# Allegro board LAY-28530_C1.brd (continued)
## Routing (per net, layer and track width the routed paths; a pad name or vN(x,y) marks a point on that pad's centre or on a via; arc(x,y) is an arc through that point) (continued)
LANED_RX_N: length 90.8
  TOP w0.104: v1(127.9,83.87) 127.81,83.77 127.66,83.77 127.5,83.93 127.5,87.74 131.68,91.92 131.68,117.7 135.74,121.76 135.74,129.54 132.75,132.53 132.11,132.53 C30.1 ; U21.AB14 133,62.41 132.6,62.02 130.77,62.02 130.76,62.02 129.77,62.02 128.37,60.63 126.76,60.63 125.99,61.39 125.99,63.37 127.26,64.64 127.26,64.87 v1(127.06,65.07)
  L3_INT1 w0.104: v1(127.9,83.87) 127.79,83.87 127.48,84.18 127.48,84.48 127.07,84.88 126.42,84.88 125.91,84.38 125.91,83.36 126.29,82.98 126.79,82.98 127.82,81.95 127.82,67.37 127.25,66.81 127.25,65.27 v1(127.06,65.07)
LANED_RX_P: length 87.4
  TOP w0.104: U21.AC14 132.2,62.41 132.03,62.24 131.76,62.24 131.67,62.33 130.77,62.33 130.76,62.32 129.64,62.32 128.25,60.93 126.88,60.93 126.29,61.52 126.29,63.25 127.56,64.52 127.56,64.82 v1(127.82,65.07) ; C37.1 132.11,132.23 132.62,132.23 135.44,129.42 135.44,121.89 131.37,117.82 131.37,92.04 127.2,87.87 127.2,84.14 126.93,83.87 v1(126.8,83.87)
  L3_INT1 w0.104: v1(126.8,83.87) 127.11,84.18 127.11,84.32 126.92,84.51 126.58,84.51 126.28,84.22 126.28,83.51 126.45,83.35 126.94,83.35 128.19,82.1 128.19,67.22 127.62,66.65 127.62,65.27 v1(127.82,65.07)
LANED_TX_N: length 82.1
  TOP w0.104: v1(126.51,82.47) 126.11,82.87 126.11,88 130.53,92.43 130.53,118.54 134.73,122.73 134.73,129.41 133.23,130.91 129.68,130.91 128.2,132.38 127.59,132.38 U6.39
  L3_INT1 w0.104: v1(126.51,82.47) 126.16,82.12 126.16,70.94 127.06,70.04 127.06,67.74 v1(127.18,67.61)
  BOTTOM w0.104: C417.1 129.09,62.09 128.98,61.98 128.49,61.98 128.33,62.15 128.33,62.66 126.6,64.39 126.6,65.25 126.95,65.6 126.95,67.38 v1(127.18,67.61)
LANED_TX_P: length 82.1
  TOP w0.104: U6.38 128.17,131.98 129.55,130.6 133.11,130.6 134.42,129.29 134.42,122.86 130.23,118.67 130.23,92.55 125.8,88.12 125.8,82.87 v1(125.41,82.47)
  L3_INT1 w0.104: v1(125.41,82.47) 125.79,82.09 125.79,70.79 126.69,69.89 126.69,67.88 v1(126.42,67.61)
  BOTTOM w0.104: v1(126.42,67.61) 126.65,67.38 126.65,65.73 126.29,65.37 126.29,64.26 128.02,62.53 128.02,62.03 128.37,61.68 128.98,61.68 129.09,61.58 C429.1
LDO_1V0: length 27.5
  TOP w0.305: U26.4 108.01,55.04 v1(108.26,55.29)
  TOP w0.508: 110.29,54.91 R137.2 111.82,56.56 v1(115.75,60.5)
  BOTTOM w0.381: R309.2 v1(120.33,70.91)
  BOTTOM w0.508: FL1.3 116.22,60.97 v1(115.75,60.5) 115.12,60.5 114.48,61.14 114.48,63.04 116.13,64.69 116.13,69.19 117.4,70.46 119.87,70.46 v1(120.33,70.91)
LED_G-: length 25.2
  TOP w0.305: J3.16 144.71,163.16 144.71,154.23 144.33,153.85 144.33,146.1 145.09,145.34 C18.1 R26.2
LED_GY+: length 44.2
  TOP w0.254: J3.17 144.48,165.92 146.27,164.13 157.72,164.13 J3.19
  TOP w0.508: J3.17 142.95,165.93 141.28,164.26 L10.2
LED_Y-: length 26.2
  TOP w0.305: J3.18 159.31,163.19 159.31,150.29 165.28,144.32 C16.1 R24.2
MPCIE1_CLK+: length 43.7
  TOP w0.104: P3.13 57.22,126.78 57.47,126.53 57.98,126.53 59.11,125.4 59.11,94.79 61.83,92.08 61.83,88.8 61.93,88.69 R352.1 R351.2
MPCIE1_CLK-: length 43.3
  TOP w0.104: P3.11 57.15,125.98 57.4,126.23 57.85,126.23 58.81,125.27 58.81,94.67 61.52,91.95 61.52,88.82 61.4,88.69 R358.1 R357.2
MPCIE2_CLK+: length 28.6
  TOP w0.104: P2.13 43.55,65.01 43.8,65.25 43.8,65.68 44.25,66.14 59.24,66.14 61.1,67.99 61.1,73.96 60.97,74.09 R334.1 R333.2
MPCIE2_CLK-: length 28.6
  TOP w0.104: R347.2 R348.1 61.52,74.09 61.4,73.96 61.4,67.87 59.37,65.83 44.38,65.83 44.1,65.56 44.1,65.22 44.35,64.97 P2.11
NAND_BOOT_SEL: length 54.8
  TOP w0.127: v1(179.9,89.59) 179.89,89.6 179.89,90.73
  TOP w0.152: v1(203,58.24) 203,58.25 SW3.4
  L3_INT1 w0.127: v1(179.9,89.59) 181.03,90.73 194.62,90.73 203,82.34 v1(203,58.24)
  BOTTOM w0.127: U15.1 v1(179.9,89.59)
NAND_CS: length 22.6
  TOP w0.127: U16.C6 v2(195.26,86.26)
  L3_INT1 w0.127: v1(182.5,89.46) 183.39,90.35 194.49,90.35 195.64,89.2 195.64,86.64 v2(195.26,86.26)
  BOTTOM w0.152: v1(182.5,89.46) U15.5 182.5,91.93 182.3,92.12 181.41,92.12 181.2,91.91 U15.3
NAND_RB: length 15.4
  TOP w0.152: v1(182.56,83.49) 183.44,82.6 193.73,82.6 194.63,83.49 U16.C8
  BOTTOM w0.152: U15.12 182.5,83.54 v1(182.56,83.49)
NOR_CS: length 21
  TOP w0.152: v1(177.39,77.43) U20.32
  L3_INT1 w0.127: v1(177.39,77.43) 178.75,78.79 178.75,86.76 v1(180.55,88.57)
  BOTTOM w0.152: v1(180.55,88.57) U15.2 180.55,92.15 180.9,92.5 182.68,92.5 183.15,92.04 U15.6
NOR_RB: length 21.6
  TOP w0.152: U20.17 v1(199.3,73.43)
  L3_INT1 w0.122: 190.52,82.22 189.25,83.49 186.37,83.49
  L3_INT1 w0.127: v1(199.3,73.43) 190.52,82.22 ; 186.37,83.49 v1(184.46,83.49)
  BOTTOM w0.127: U15.9 184.45,83.5 v1(184.46,83.49)
NUART_CTS: length 10.4
  TOP w0.152: L3.2 184.84,155.12 180.57,159.39 P1.8
NUART_RTS: length 23.2
  TOP w0.152: P1.1 173.43,165.93 173.79,166.29 180.02,166.29 181.79,164.51 181.79,158.8 185.48,155.12 185.48,153.97 L5.2
PCIE_3V3: length 13
  TOP w0.508: P2.24 v1(35.95,57.41) ; P2.39 v1(29.95,62.07) ; P2.52 v1(24.75,57.33) ; P2.41 v1(29.15,62.04) ; P2.2 v1(47.95,57.44)
  BOTTOM w0.381: C306.1 36,57.36 v1(35.95,57.41) ; v1(24.75,57.33) 24.82,57.25 C307.1 ; v1(47.95,57.44) 48.06,57.33 48.06,56.56
  BOTTOM w0.508: C300.1 29.06,61.95 v1(29.15,62.04)
  vias: v1(72.7,50.47) v1(72.7,49.07) v1(73.34,49.83) v1(73.97,50.47) v1(73.97,49.07)
POE_12V: length 41.2
  TOP w0.508: v1(68.76,110.67) 68.13,110.03 R235.2 ; D10.A v1(83.5,95.43)
  L3_INT1 w0.508: v1(86.16,113.46) 83.5,110.79 v1(83.5,95.43)
  BOTTOM w0.508: v1(68.76,110.67) 70.29,112.19 82.1,112.19 82.61,112.7 R61.1 v1(86.16,113.46)
PORESET: length 47.8
  TOP w0.127: U21.B5 149,69.61 v2(149.4,70.01)
  L4_INT2 w0.127: v2(149.4,70.01) 149.92,70.53 157.16,70.53 157.92,69.77 157.92,62.66 169.35,51.23 v1(169.35,49.45)
  BOTTOM w0.152: Q24.3 Q25.3 R356.2 171.89,46.91 v1(169.35,49.45)
RESET: length 481.3
  TOP w0.152: U3.2 207.64,143.62 R15.1 207.7,142.8 v1(207.45,142.54) ; U6.13 121.17,135.98 120.96,136.19 120.96,137.59 121.21,137.84 v1(121.21,138.48) ; P2.22 v1(36.75,58.98) ; U5.13 99.84,135.98 v1(99.62,136.19) ; v1(206.18,31.29) 206.69,31.8 Q11.2 ; P3.22 v1(50.3,133.58) ; Q13.2 v1(195.64,13.71)
  L3_INT1 w0.127: v1(207.45,142.54) 206.94,142.54 203.76,139.37 203.76,97.33 210.5,90.6 210.5,63.8 209.35,62.66 209.35,36.75 206.18,33.58 v1(206.18,31.29) ; v1(99.62,136.19) 98.48,137.34 86.04,137.34 85.02,138.35 60,138.35 58.86,139.49 53.02,139.49 51.49,137.97 51.49,134.77 v1(50.3,133.58) 50.3,125.83 53.65,122.48 53.65,95.04 56.19,92.5 56.19,70.28 53.02,67.1 32.19,67.1 31.68,66.6 31.68,62.28 34.98,58.98 v1(36.75,58.98)
  L4_INT2 w0.127: v1(208.72,147.57) 208.26,147.11 171.25,147.11 168.2,144.07 142.04,144.07 137.22,139.24 123.75,139.24 122.99,138.48 v1(121.21,138.48) 120.2,139.49 116.64,139.49 115.88,138.73 111.82,138.73 109.28,136.19 v1(99.62,136.19)
  BOTTOM w0.152: v1(207.45,142.54) 207.7,142.8 Q15.2 208.59,147.7 v1(208.72,147.57) 209.28,147.57 210.24,146.61 212.65,146.61 212.91,146.86 Q14.2 ; Q25.2 174.17,37.89 176.59,35.48 182.94,35.48 184.59,33.83 200.97,33.83 203.51,31.29 v1(206.18,31.29) 206.18,20.5 199.4,13.71 v1(195.64,13.71)
RS232_CTS0: length 3
  TOP w0.152: L3.1 183.07,154.48 182.95,154.35 v1(182.94,154.35) 182.94,154.34 182.43,153.84 U2.8
RS232_RTS0: length 2.8
  TOP w0.152: L5.1 v1(182.68,153.34) 182.53,153.18 U2.7
RS232_RXD0: length 2.3
  TOP w0.152: U2.13 172.59,151.23 172.4,151.43 L6.1
RS232_TXD0: length 2.4
  TOP w0.152: L7.1 172.4,150.29 172.69,150.58 U2.14
RTC_INT_N: length 64.3
  TOP w0.152: U10.7 107.94,114.15 v1(108.01,114.22) 108.13,114.35 108.13,115.11 ; U21.R4 v2(138.19,70.81)
  L3_INT1 w0.127: v1(108.01,114.22) 108.64,114.22 112.71,110.16 112.71,102.41 126.8,88.31 129.98,88.31 131.88,86.41 131.88,82.47 132.77,81.58 132.77,79.8 133,79.58 133,70.56 133.15,70.41 136.76,70.41 136.77,70.41 137.79,70.41 v2(138.19,70.81)
RTC_XI: length 4
  TOP w0.254: Y4.1 106.48,106.73 107.29,107.53 U10.1
RTC_XO: length 4.2
  TOP w0.254: U10.2 107.94,107.56 109.02,106.47 Y4.2
SD_CLK: length 22.5
  TOP w0.152: U32.3 v1(185.44,23.58) ; v1(181.75,27.65) U30.8 U30.1 181.75,31.12 182.3,31.67 v1(182.3,31.71)
  BOTTOM w0.152: v1(182.3,31.71) 184.04,31.71 184.43,31.32 184.43,30 J16.5 ; v1(185.44,23.58) 183,23.58 182.85,23.74 182.85,23.9 183,24.05 183.93,24.05 184.08,24.2 184.08,24.41 183.93,24.56 182.07,24.56 181.92,24.71 181.92,24.91 182.07,25.07 183.95,25.07 184.08,25.19 184.08,25.45 183.95,25.58 182.58,25.58 181.75,26.41 v1(181.75,27.65)
SD_CLK1_N: length 37.3
  TOP w0.104: R113.2 103.82,80.37 103.92,80.48 105.11,80.48 105.21,80.37 ; 105.21,80.37 R114.1 ; 105.21,80.37 105.32,80.48 107.41,80.48 108.13,79.76 108.13,78.28 109.02,77.39 112.03,77.39 119.82,69.6 123.04,69.6 124.39,68.25 131.17,68.25 131.25,68.17 131.25,68.17 131.81,67.61 132.6,67.61 U21.AB7
SD_CLK1_P: length 36.5
  TOP w0.104: 131.46,68.38 131.36,68.49 131.36,68.49 131.3,68.55 124.52,68.55 123.17,69.9 119.95,69.9 112.15,77.69 109.15,77.69 108.44,78.4 108.44,79.88 107.54,80.78 105.32,80.78 105.21,80.89 ; 105.21,80.89 R111.1 ; 105.21,80.89 105.11,80.78 103.92,80.78 103.82,80.89 R110.2 ; U21.AC7 132.03,67.84 131.91,67.84 131.63,68.12 131.63,68.22
  TOP w0.127: 131.63,68.22 131.46,68.38
SD_CLK2_N: length 40.4
  TOP w0.102: 131.38,60.37 132.08,60.37 132.09,60.38 132.35,60.38 132.78,60.81 133,60.81 U21.AB16
  TOP w0.104: 105.34,76.44 105.44,76.54 111.14,76.54 123.45,64.23 123.45,61.06 124.95,59.56 129.09,59.56 129.9,60.37 131.37,60.37 ; 105.34,76.44 R122.1 ; 105.34,76.44 105.24,76.54 103.92,76.54 103.82,76.44 R121.2
SD_CLK2_P: length 39.5
  TOP w0.102: U21.AC16 132.2,60.81 131.99,60.6 131.47,60.6 131.4,60.68 131.37,60.68
  TOP w0.104: 131.37,60.68 129.77,60.68 128.96,59.87 125.07,59.87 123.75,61.18 123.75,64.36 111.27,76.84 105.44,76.84 105.34,76.95 ; 105.34,76.95 R117.1 ; 105.34,76.95 105.24,76.84 103.92,76.84 103.82,76.95 R116.2
SD_CMD: length 23.7
  TOP w0.152: v1(181.03,31.67) 181.25,31.45 U30.2 U30.7 181.25,26.75 182.47,25.53 U32.6
  BOTTOM w0.152: J16.2 191.93,28.85 191.57,28.5 186.37,28.5 185.73,29.13 185.73,31.04 184.33,32.43 181.79,32.43 v1(181.03,31.67)
SD_D0: length 22
  TOP w0.152: v1(179.89,31.67) 180.05,31.51 U30.3 U30.6 180.05,28.08 180.14,27.99 180.73,27.99 180.85,27.86 180.85,27.68 180.65,27.48 179.48,27.48 179.35,27.35 179.35,27.13 179.51,26.97 180.31,26.97 182.02,25.26 182.02,25.04 181.91,24.93 181.7,24.93 180.07,26.56 179.73,26.56 179.61,26.44 179.61,26.23 180.14,25.71 180.15,25.71 181.25,24.61 181.25,24.39 181.14,24.29 180.93,24.29 179.03,26.18 178.11,26.18
  BOTTOM w0.152: J16.7 179.5,30 179.5,31.28 v1(179.89,31.67)
SD_D1: length 22.6
  TOP w0.152: v1(178.62,31.63) 178.92,31.63 179.55,30.99 U30.4 U30.5 179.55,28.41 v1(179.38,28.24) ; 178.11,24.23 v1(176.91,24.23)
  BOTTOM w0.152: v1(179.38,28.24) 179.38,27.51 178.72,26.85 176.46,26.85 176.33,26.72 176.33,26.46 176.46,26.34 178.97,26.34 179.13,26.18 179.13,25.98 178.97,25.83 176.59,25.83 176.46,25.7 176.46,25.45 176.59,25.32 178.47,25.32 178.62,25.17 178.62,24.97 178.47,24.81 177.09,24.81 176.91,24.63 v1(176.91,24.23) ; J16.8 177.8,31.1 178.32,31.63 v1(178.62,31.63)
SD_D2: length 23.2
  TOP w0.152: v1(194.11,32.05) 193.43,31.37 U31.1 U31.8 v1(193.43,28.79) ; U33.3 v1(195.72,23.58)
  BOTTOM w0.152: J16.9 196.93,30 196.93,31.14 196.02,32.05 v1(194.11,32.05) ; v1(193.43,28.79) 194.11,28.12 194.11,26.59 193.86,26.34 191.98,26.34 191.83,26.18 191.83,25.98 191.98,25.83 193.71,25.83 193.86,25.68 193.86,25.52 193.71,25.37 192.11,25.37 191.95,25.22 191.95,24.97 192.11,24.81 194.49,24.81 v1(195.72,23.58)
SD_D3: length 19.1
  TOP w0.152: U33.6 191,25.53 190.74,25.8 190.74,26.01 190.94,26.21 192.33,26.21 192.59,26.46 192.59,26.85 192.46,26.97 190.56,26.97 190.43,27.1 190.43,27.61 190.56,27.73 192.59,27.73 192.93,28.08 U31.7 U31.2 192.93,31.71 v1(192.72,31.93)
  BOTTOM w0.152: J16.1 194.43,30 194.43,31.1 194.11,31.42 193.22,31.42 v1(192.72,31.93)
SDHC_CD_N: length 91.3
  TOP w0.127: U21.H3 v2(144.6,71.61)
  TOP w0.152: R156.1 v1(191.19,31.93) 191.32,31.93 191.74,31.51 U31.3 U31.6 ; v1(198.56,31.29) 198.63,31.37 Q29.3
  L3_INT1 w0.127: v1(191.19,31.93) 192.97,30.15 197.41,30.15 v1(198.56,31.29)
  L4_INT2 w0.127: v2(144.6,71.61) 144.65,71.61 145.05,71.21 157.75,71.21 158.62,70.34 158.62,62.98 170.24,51.36 170.24,37.89 175.32,32.81 190.3,32.81 v1(191.19,31.93)
  BOTTOM w0.152: J16.3A 190.23,30.96 v1(191.19,31.93)
SDHC_CLK: length 83.1
  TOP w0.152: U32.4 185.15,24.23 185.48,24.56 185.48,30.91 184.71,31.67 R160.2 185.73,32.81 185.98,33.07 v1(185.98,35.61)
  L4_INT2 w0.127: v1(158.55,76.88) 159.82,75.61 159.82,73.2 161.22,71.8 161.22,64.82 163,63.04 166.05,63.04 166.17,62.91 166.17,62.66 166.05,62.53 164.14,62.53 164.01,62.41 164.01,62.15 164.14,62.02 166.05,62.02 166.17,61.9 166.17,61.64 166.05,61.52 165.28,61.52 165.16,61.39 165.16,61.14 165.28,61.01 166.81,61.01 166.93,60.88 166.93,60.63 166.81,60.5 166.17,60.5 166.05,60.37 166.05,60.12 166.17,59.99 167.19,59.99 167.32,59.87 167.32,58.72 172.9,53.13 172.9,39.55 177.09,35.35 185.73,35.35 v1(185.98,35.61)
  BOTTOM w0.152: R282.1 158.17,77.26 v1(158.55,76.88)
SDHC_CMD: length 94.5
  TOP w0.127: U21.J2 v2(143.8,72.41)
  TOP w0.152: v1(181.92,33.7) 181.92,33.2 182.3,32.81 R159.2 183.06,28.12 182.17,27.23 182.17,26.72 182.71,26.18 U32.7
  L4_INT2 w0.127: v2(143.8,72.41) 144.2,72.81 150.69,72.81 151.57,71.93 158.3,71.93 159.31,70.91 159.31,64.31 171,52.63 171,38.15 175.57,33.58 179.25,33.58 179.38,33.7 179.38,34.08 179.51,34.21 179.76,34.21 179.89,34.08 179.89,33.7 180.02,33.58 180.27,33.58 180.4,33.7 180.4,34.08 180.52,34.21 180.78,34.21 180.9,34.08 180.9,33.7 181.03,33.58 181.29,33.58 181.41,33.7 181.41,34.08 181.54,34.21 188.65,34.21 188.78,34.08 188.78,33.83 188.65,33.7 v1(181.92,33.7)
SDHC_D0: length 96.1
  TOP w0.127: U21.J1 v2(143.8,73.21)
  TOP w0.152: v1(178.75,34.08) 178.75,33.45 178.11,32.81 R158.2 176.84,32.18 176.84,31.8 176.97,31.67 177.73,31.67 177.86,31.54 177.86,31.29 177.73,31.16 176.97,31.16 176.84,31.04 176.84,30.78 176.97,30.66 178.47,30.66 178.62,30.5 178.62,30.27 178.36,30.02 176.97,30.02 176.84,29.89 176.84,29.51 176.97,29.39 178.36,29.39 178.49,29.26 178.49,29 178.36,28.88 176.97,28.88 176.84,28.75 176.84,28.37 176.97,28.24 177.98,28.24 178.11,28.12 178.11,27.86 177.98,27.73 177.09,27.73 176.84,27.48 176.84,27.1 177.11,26.84 178.11,26.84
  L4_INT2 w0.127: v1(178.75,34.08) 178.49,33.83 175.82,33.83 171.38,38.28 171.38,52.75 159.7,64.44 159.7,71.04 157.54,73.2 157.28,73.2 157.16,73.07 157.16,72.44 157.03,72.31 156.77,72.31 156.65,72.44 156.65,73.45 156.39,73.71 155.5,73.71 155.38,73.58 155.38,72.44 155.25,72.31 155,72.31 154.87,72.44 154.87,73.45 154.62,73.71 153.73,73.71 153.6,73.58 153.6,72.44 153.47,72.31 153.22,72.31 153.09,72.44 153.09,73.58 152.96,73.71 152.71,73.71 152.58,73.58 152.58,72.44 152.46,72.31 152.2,72.31 152.08,72.44 152.08,73.58 151.95,73.71 151.69,73.71 151.57,73.58 151.57,73.07 151.44,72.95 151.19,72.95 151.06,73.07 151.06,73.58 150.93,73.71 150.68,73.71 150.55,73.58 150.55,73.33 150.42,73.2 150.17,73.2 150.04,73.33 150.04,73.58 149.92,73.71 147.38,73.71 147.25,73.58 147.25,73.33 147.12,73.2 146.87,73.2 146.74,73.33 146.74,73.58 146.61,73.71 144.3,73.71 v2(143.8,73.21)
SDHC_D1: length 95.5
  TOP w0.127: U21.K2 v2(143,72.41)
  TOP w0.152: 178.11,24.88 177.15,24.88 176.46,25.58 176.46,31.8 R157.2 174.81,32.81 174.43,33.2 174.43,34.34 174.3,34.47 173.82,34.47 173.67,34.62 173.67,34.85 173.79,34.97 174.3,34.97 174.43,35.1 174.43,35.35 174.3,35.48 173.79,35.48 173.67,35.61 173.67,35.86 173.79,35.99 174.3,35.99 174.43,36.12 v1(174.43,36.88)
  L4_INT2 w0.127: v1(174.43,36.88) 172.14,39.16 172.14,52.88 160.46,64.56 160.46,71.3 157.16,74.6 156.52,74.6 156.39,74.72 156.39,75.23 156.27,75.36 156.01,75.36 155.89,75.23 155.89,74.72 155.76,74.6 155.5,74.6 155.38,74.72 155.38,75.36 155.25,75.49 155,75.49 154.87,75.36 154.87,74.72 154.74,74.6 154.49,74.6 154.36,74.72 154.36,75.36 154.23,75.49 153.98,75.49 153.85,75.36 153.85,74.72 153.73,74.6 153.47,74.6 153.35,74.72 153.35,75.36 153.22,75.49 152.96,75.49 152.84,75.36 152.84,74.72 152.71,74.6 152.46,74.6 152.33,74.72 152.33,75.36 152.2,75.49 151.95,75.49 151.82,75.36 151.82,74.72 151.69,74.6 151.44,74.6 151.31,74.72 151.31,75.36 151.19,75.49 150.93,75.49 150.81,75.36 150.81,74.85 150.55,74.6 150.04,74.6 149.79,74.85 149.79,75.36 149.66,75.49 149.41,75.49 149.28,75.36 149.28,74.72 149.15,74.6 148.9,74.6 148.77,74.72 148.77,75.23 148.65,75.36 148.39,75.36 148.27,75.23 148.27,74.72 148.14,74.6 147.88,74.6 147.76,74.72 147.76,75.36 147.63,75.49 147.38,75.49 147.25,75.36 147.25,74.72 147.12,74.6 146.87,74.6 146.74,74.72 146.74,75.36 146.61,75.49 146.36,75.49 146.23,75.36 146.23,74.72 146.11,74.6 145.85,74.6 145.73,74.72 145.73,75.36 145.6,75.49 145.34,75.49 145.22,75.36 145.22,74.72 145.09,74.6 144.84,74.6 144.71,74.72 144.71,75.23 144.58,75.36 144.33,75.36 144.2,75.23 144.2,74.72 144.07,74.6 143.69,74.6 142.59,73.5 142.59,72.81 v2(143,72.41)
SDHC_D2: length 96.4
  TOP w0.127: U21.K1 v2(143,73.21)
  TOP w0.152: U33.4 195.44,24.23 196.14,24.94 196.14,32.05 R162.2 v1(197.92,32.81)
  L4_INT2 w0.127: v1(197.92,32.81) 197.16,33.58 189.92,33.58 188.91,34.59 175.82,34.59 171.76,38.66 171.76,52.75 160.08,64.44 160.08,71.17 157.03,74.22 144,74.22 v2(143,73.21)
SDHC_D3: length 96.4
  TOP w0.127: U21.L1 v2(142.2,73.21)
  TOP w0.152: U33.7 195.36,26.18 195.76,26.59 195.76,32.18 R161.2 194.24,32.81 193.73,33.32 v1(193.73,34.34)
  L4_INT2 w0.127: v2(142.2,73.21) 142.2,73.86 144.2,75.87 156.39,75.87 160.84,71.42 160.84,64.69 172.52,53.01 172.52,39.42 176.97,34.97 189.67,34.97 189.79,34.85 189.79,34.47 189.92,34.34 190.18,34.34 190.3,34.47 190.3,34.85 190.43,34.97 190.81,34.97 190.94,34.85 190.94,34.47 191.06,34.34 191.32,34.34 191.45,34.47 191.45,34.85 191.57,34.97 191.95,34.97 192.08,34.85 192.08,34.34 192.21,34.21 192.46,34.21 192.59,34.34 192.59,34.85 192.72,34.97 193.1,34.97 v1(193.73,34.34)
SDHC_VS: length 29.5
  TOP w0.127: v2(148.6,70.01) 148.19,69.61 U21.C5
  BOTTOM w0.127: v2(148.6,70.01) 148.63,70.01 149.15,70.53 149.79,70.53
  BOTTOM w0.152: 149.79,70.53 150.68,71.42 150.68,71.93 154.49,75.74 159.57,75.74 162.62,78.79 R270.2 163.51,78.28 163.63,78.15 166.68,78.15 168.46,79.93 R266.1
SDHC_WP_N: length 108.2
  TOP w0.127: U21.H4 v2(144.6,70.81)
  TOP w0.152: v1(198.43,27.23) 198.48,27.18 Q30.3 ; R155.1 189.54,32.31 v1(189.92,31.93) 190.3,31.54 190.68,31.54 191.24,30.99 U31.4 U31.5
  L3_INT1 w0.127: v1(198.43,27.23) 195.89,29.77 192.08,29.77 v1(189.92,31.93)
  L4_INT2 w0.127: v1(189.92,31.93) 189.41,32.43 175.19,32.43 169.86,37.77 169.86,51.23 158.3,62.79 158.3,70.03 157.41,70.91 149.41,70.91 148.9,70.41 148.76,70.41 148.76,70.41 145,70.41 v2(144.6,70.81)
  BOTTOM w0.152: J16.10 174.31,31.04 176.21,32.94 188.91,32.94 v1(189.92,31.93)
SGMII_AVDD10: length 23.7
  TOP w0.203: U6.4 v1(125.64,137.7) ; v1(128.58,135.68) 128.48,135.58 U6.47 ; U6.9 v1(123.64,137.72)
  TOP w0.508: R64.2 v1(133.91,127.81)
  L4_INT2 w0.508: v1(125.64,137.7) 125.8,137.7 127.82,135.68 v1(128.58,135.68)
  BOTTOM w0.508: v1(125.64,137.7) 125.53,137.59 C199.2 C200.2 123.63,137.68 123.64,137.7 v1(123.64,137.72) ; C214.2 v1(128.58,135.68) 128.58,135.56 131.25,132.89 132.64,132.89 134.68,130.86 134.68,128.57 v1(133.91,127.81)
SGMII_DVDD10: length 19.6
  TOP w0.203: U6.22 v1(120.58,132.38)
  TOP w0.508: R71.2 v1(133.91,126.16)
  L4_INT2 w0.508: v1(133.91,126.16) 132.26,127.81 123.88,127.81 120.58,131.11 v1(120.58,132.38)
  BOTTOM w0.508: C221.2 120.58,132.51 v1(120.58,132.38)
SGMII_DVDD_3V3: length 20.7
  TOP w0.203: v1(124.28,128.67) 124.39,128.78 124.39,128.83 124.44,128.88 U6.30
  TOP w0.508: R58.2 133.28,129.33 v1(133.79,128.83)
  L4_INT2 w0.381: v1(133.79,128.83) 133.52,128.56 129.99,128.56 128.83,129.72 125.33,129.72 v1(124.28,128.67)
  BOTTOM w0.508: C230.2 124.77,129.33 124.28,128.84 v1(124.28,128.67) 123.53,128.67 123.37,128.83 C241.1 R220.2 ; R218.2 133.03,128.45 133.41,128.45 v1(133.79,128.83)
SGMII_DVDDRG: length 22
  TOP w0.203: U6.29 124.04,129.82 123.8,129.58 v1(123.77,129.58)
  TOP w0.508: R67.2 124.14,125.14 122.87,123.87 121.6,123.87 v1(120.83,124.64) R69.2 119.82,125.91 118.17,127.56 R56.2
  L3_INT1 w0.508: v1(123.77,129.58) 123.37,129.18 123.37,127.18 v1(120.83,124.64)
  BOTTOM w0.508: C233.1 123.37,130.6 C228.2 123.5,129.85 v1(123.77,129.58)
SGMII_LED0/PHYAD0: length 199.4
  TOP w0.152: U6.35 126.44,130.2 126.93,129.72 129.34,129.72 129.72,129.33 v1(130.23,129.33) R58.1
  TOP w0.305: J5.17 119.18,140.1 v1(119.18,138.99) C20.1
  L4_INT2 w0.203: v1(127.82,8.68) 111.82,8.68 110.17,10.34 110.17,12.11 106.1,16.18 106.1,35.1 110.29,39.29 110.29,44.88 112.71,47.29 112.71,63.42 109.91,66.22 109.91,90.47 115.35,95.91 128.05,95.91 130.38,98.24 130.38,117.67 135.31,122.6 135.31,128.32 134.04,129.59 130.49,129.59 v1(130.23,129.33)
  L4_INT2 w0.254: v1(119.18,138.99) 121.09,137.08 125.28,137.08 128.33,134.03 128.33,131.87 129.47,130.73 129.47,129.97 130.1,129.33 v1(130.23,129.33)
  BOTTOM w0.203: v1(127.82,8.68) C603.1
  BOTTOM w0.254: D13.4 127.82,5.74 v1(127.82,8.68)
SGMII_LED1/CFG_LDO0: length 184
  TOP w0.152: v1(130.23,130.1) 127.07,130.1 126.84,130.32 U6.36 ; R32.1 139.76,136.57 140.01,136.83 v1(140.01,137.84)
  L3_INT1 w0.127: v1(130.23,130.1) 137.98,137.84 v1(140.01,137.84)
  L4_INT2 w0.203: v1(122.61,9.32) 111.94,9.32 110.67,10.59 110.67,12.24 106.48,16.43 106.48,33.32 110.67,37.51 110.67,44.63 113.09,47.04 113.09,63.68 110.29,66.47 110.29,90.22 115.63,95.55 128.2,95.55 130.74,98.09 130.74,117.52 135.69,122.48 135.69,128.57 134.17,130.1 v1(130.23,130.1)
  BOTTOM w0.152: R213.2 130.74,129.59 v1(130.23,130.1)
  BOTTOM w0.203: v1(122.61,9.32) 122.61,10.97 123.37,11.73 R394.1
SGMII_LED2/CFG_LDO1: length 5.4
  TOP w0.152: v1(128.33,130.86) 128.33,131.37 128.11,131.58 U6.37
  BOTTOM w0.152: v1(128.33,130.86) 128.33,130.35 R218.1
SGMII_MDIN0: length 10
  TOP w0.104: U6.3 126.04,137.39 126.09,137.44 126.09,138.3 v1(125.91,138.48)
  L3_INT1 w0.104: J5.10 129.56,144.36 129.86,144.06 129.86,143.58 128.58,142.3 128.58,141.4 126.18,139 126.18,138.74 v1(125.91,138.48)
SGMII_MDIN1: length 14.9
  TOP w0.104: U6.6 124.84,137.39 124.89,137.44 124.89,140.01 v1(124.77,140.13)
  L3_INT1 w0.104: v1(124.77,140.13) 124.91,139.99 124.91,139.56 125.23,139.24 125.79,139.24 127.55,141.01 127.55,144.42 129.22,146.08 129.22,146.73 129.38,146.9 J5.5
SGMII_MDIN2: length 12.5
  TOP w0.104: U6.8 124.04,137.39 124.09,137.44 124.09,138.12 v1(123.73,138.48)
  L3_INT1 w0.104: v1(123.73,138.48) 123.75,138.48 123.9,138.63 123.9,140.42 126.05,142.57 126.05,144.8 124.78,146.07 124.78,146.59 124.48,146.9 J5.2
SGMII_MDIN3: length 11.3
  TOP w0.104: U6.11 122.84,137.39 122.89,137.44 122.89,139.21 v1(122.48,139.62)
  L3_INT1 w0.104: J5.9 124.56,144.36 124.14,143.94 124.14,143.56 123.5,142.92 122.88,142.92 122.36,142.4 122.36,140.37 121.98,139.99 121.98,139.38 122.26,139.1 122.59,139.1 122.74,139.26 122.74,139.36 v1(122.48,139.62)
SGMII_MDIP0: length 10
  TOP w0.104: v1(126.68,138.48) 126.39,138.2 126.39,137.44 126.44,137.39 U6.2
  L3_INT1 w0.104: v1(126.68,138.48) 126.55,138.61 126.55,138.84 128.95,141.25 128.95,142.15 130.23,143.43 130.23,144.06 130.53,144.36 J5.11
SGMII_MDIP1: length 13.8
  TOP w0.104: U6.5 125.24,137.39 125.2,137.44 125.2,139.79 v1(125.53,140.13)
  L3_INT1 w0.104: v1(125.53,140.13) 125.28,139.88 125.28,139.72 125.38,139.61 125.63,139.61 127.18,141.16 127.18,144.57 128.85,146.24 128.85,146.6 128.54,146.9 J5.4
SGMII_MDIP2: length 12.4
  TOP w0.104: v1(124.45,138.48) 124.4,138.43 124.4,137.44 124.44,137.39 U6.7
  L3_INT1 w0.104: v1(124.45,138.48) 124.27,138.65 124.27,140.27 126.42,142.42 126.42,144.96 125.15,146.22 125.15,146.61 125.45,146.9 J5.3
SGMII_MDIP3: length 12.5
  TOP w0.104: v1(123.37,139.62) 123.2,139.44 123.2,137.44 123.24,137.39 U6.10
  L3_INT1 w0.104: v1(123.37,139.62) 123.11,139.36 123.11,139.11 122.74,138.73 122.1,138.73 121.61,139.23 121.61,140.14 121.99,140.52 121.99,142.55 122.73,143.29 123.35,143.29 123.77,143.72 123.77,144.05 123.46,144.36 J5.8
SGMII_PHY_INT_N: length 77.2
  TOP w0.127: U21.D5 v2(147.8,70.01)
  TOP w0.152: v1(128.2,129.08) 127.06,129.08 126.04,130.09 U6.34
  L3_INT1 w0.127: v1(142.42,80.57) 141.03,80.57 138.36,83.23 138.36,91.11 133.15,96.31 133.15,125.52 129.6,129.08 v1(128.2,129.08)
  BOTTOM w0.127: 148.2,73.58 148.2,72.25 148.19,72.25 148.19,70.41 v2(147.8,70.01)
  BOTTOM w0.152: v1(142.42,80.57) 142.93,81.07 147.25,81.07 147.88,80.44 147.88,78.28 148.01,78.15 R272.2 148.52,74.41 148.2,74.09 148.2,73.58
SGMII_RXC/PHYAD1: length 3.9
  TOP w0.152: R67.1 123.18,128.51 123.18,129.78 123.64,130.24 U6.28
SGMII_RXCTL/PHYAD2: length 3.7
  TOP w0.152: R68.2 122.48,129.59 123.24,130.35 U6.27
SGMII_RXD1/CFG_MODE0: length 4.4
  TOP w0.152: U6.25 122.44,130.06 121.85,129.46 121.34,129.46 120.83,128.95 R69.1
SGMII_RXD2/CFG_MODE1: length 3.2
  TOP w0.152: U6.24 121.17,131.58 120.71,131.11 120.71,130.35 120.2,129.84 R56.1
SGMII_RXD3/CFG_MODE2: length 2.3
  TOP w0.152: R51.2 120.33,131.37 120.94,131.98 U6.23
SGMII_VDDREG: length 7.2
  TOP w0.203: v1(125.32,128.7) 125.32,128.91 124.84,129.39 U6.31
  BOTTOM w0.508: R223.2 C250.1 125.32,127.9 v1(125.32,128.7) 126.04,129.42 C234.2
SPI_CLK: length 37
  TOP w0.152: U14.16 200.21,93.77 199.07,92.63 182.56,92.63 181.54,93.65 177.98,93.65 173.92,97.71 168.46,97.71 167.57,96.82 R99.2
SPI_CS: length 69.3
  TOP w0.152: v1(167.82,100.51) 191.06,100.51 192.59,102.03 v1(192.59,102.61) U14.7 ; U21.J4 v2(143.8,70.81)
  L3_INT1 w0.127: v2(143.8,70.81) 143.8,70.81 143.39,71.21 143.39,73.66 143.69,73.96 144.46,73.96 148.01,77.52 148.01,80.69 v1(167.82,100.51)
  BOTTOM w0.152: 192.59,101.65 v1(192.59,102.61)
SPI_MISO: length 68.7
  TOP w0.127: U21.M3 v2(141.4,71.61)
  TOP w0.152: U14.8 191.32,102.28 190.18,101.14 v1(169.86,101.14)
  L3_INT1 w0.127: v2(141.4,71.61) 141.4,73.7 142.42,74.72 144.2,74.72 146.74,77.26 146.74,80.69 158.68,92.63 158.68,93.65 163,97.97 164.27,97.97 167.44,101.14 v1(169.86,101.14)
SPI_MOSI: length 78.1
  TOP w0.152: U14.15 198.94,93.77 198.18,93.01 182.81,93.01 181.79,94.03 178.36,94.03 174.3,98.09 164.39,98.09 v1(164.01,98.47) ; U21.M4 v2(141.4,70.81)
  L3_INT1 w0.127: v1(164.01,98.47) 162.87,98.47 158.3,93.9 158.3,92.89 146.36,80.95 146.36,77.39 144.07,75.11 142.42,75.11 140.9,73.58 140.9,71.31 v2(141.4,70.81)
SYS_REFCLK_N: length 59.7
  TOP w0.104: R108.2 103.82,84.44 103.92,84.54 105.11,84.54 105.21,84.44 ; R109.1 105.21,84.44 ; 105.21,84.44 105.32,84.54 120.11,84.54 123.71,80.95 139.25,80.95 141.71,78.49 148.7,78.49 150.93,76.25 150.93,71.17 150.55,70.79 149.37,70.79 149,70.41 U21.B4
SYS_REFCLK_P: length 59.7
  TOP w0.104: R106.2 103.82,84.95 103.92,84.84 105.11,84.84 105.21,84.95 ; R107.1 105.21,84.95 ; 105.21,84.95 105.32,84.84 120.24,84.84 123.83,81.25 139.37,81.25 141.83,78.79 148.82,78.79 151.24,76.37 151.24,71.04 150.68,70.48 149.87,70.48 149.8,70.41 U21.A4
TEST_SEL_N: length 81.1
  TOP w0.127: U21.F8 v2(146.2,67.61)
  TOP w0.152: v1(200.72,53.13) 200.74,53.16 SW3.8
  L3_INT1 w0.127: v2(146.2,67.61) 146.6,68.01 146.6,68.61 146.8,68.81 147.23,68.81 147.4,68.98 147.4,69.38 147.63,69.61 147.63,69.61 151.79,69.61 156.39,74.22 v1(160.46,74.22) 160.71,74.47 182.81,74.47 183.32,73.96 v1(189.92,73.96)
  BOTTOM w0.152: v1(160.46,74.22) 160.71,74.22 R283.2 ; v1(200.72,53.13) 199.57,54.28 194.11,54.28 192.97,55.42 192.97,64.56 189.92,67.61 v1(189.92,73.96)
TRCT: length 63.8
  BOTTOM w0.635: J3.13 147.25,147.57 C192.2 ; J3.6 157.82,153.72 C176.2 ; J3.12 158.12,150.42 C179.2 161.98,151.31 162.43,151.75 164.58,151.75 165.16,151.18 C185.1 ; J24.7 144.71,149.24 C191.2
  BOTTOM w0.762: C187.2 143.19,150.67 145.49,152.98 J24.1 146.92,151.45 J24.7 145.9,148.91 J3.13 149.39,147.9 151.69,145.59 160.97,145.59 162.87,147.5 C185.1 ; J3.12 157.08,151.45 J3.6
UART1_CTS: length 104.6
  TOP w0.127: U21.R3 138.22,71.59 138.22,73.58
  TOP w0.152: 138.22,73.58 138.22,75.47 v1(139.63,76.88) ; U2.9 172.28,153.84 R6.1 v1(171.89,155.12)
  L3_INT1 w0.127: v1(171.89,155.12) 172.4,154.61 172.4,150.42 174.17,148.64 174.17,121.08 165.28,112.19 165.28,107.49 144.71,86.92 144.71,86.66 144.9,86.47 144.9,86.1 144.71,85.91 144.71,79.8 142.68,77.77 140.52,77.77 v1(139.63,76.88)
UART1_RTS: length 100.6
  TOP w0.127: 138.99,73.58 138.99,72.41 U21.R2
  TOP w0.152: U2.10 171.99,153.18 R7.1 v1(171.89,152.32) ; 138.99,73.58 138.99,74.22 v1(139.63,74.85)
  L3_INT1 w0.127: v1(171.89,152.32) 171.89,150.42 173.79,148.51 173.79,121.21 164.9,112.32 164.9,107.62 143.69,86.41 143.69,79.17 142.55,78.03 140.01,78.03 139.12,77.14 139.12,75.36 v1(139.63,74.85)
UART1_RXD: length 96.5
  TOP w0.127: U21.P1 139.4,73.58
  TOP w0.152: U2.12 175.5,151.88 v1(175.7,151.69) ; v1(139.63,74.09) 139.4,73.86 139.4,73.58
  L3_INT1 w0.127: v1(175.7,151.69) 174.94,150.92 174.94,120.83 166.05,111.94 166.05,107.24 145.38,86.57 145.38,85.9 145.22,85.73 145.22,79.55 142.93,77.26 141.28,77.26 140.52,76.5 140.52,74.98 v1(139.63,74.09)
UART1_TXD: length 98.1
  TOP w0.127: U21.R1 138.6,73.58
  TOP w0.152: v1(175.7,152.83) 175.4,152.53 U2.11 ; v1(139.63,75.61) 138.6,74.58 138.6,73.58
  L3_INT1 w0.127: v1(139.63,75.61) 140.14,76.12 140.14,76.63 141.03,77.52 142.8,77.52 144.96,79.68 144.96,85.82 145.14,86 145.14,86.84 165.66,107.36 165.66,112.06 174.58,120.98 174.58,151.71 v1(175.7,152.83)
UART_SIN: length 17.3
  TOP w0.152: P1.6 176.46,161.08 175.19,161.08 169.35,155.24 169.35,152.19 170.11,151.43 L6.2
UART_SOUT: length 18.4
  TOP w0.152: P1.3 175.47,162 168.97,155.5 168.97,151.69 170.36,150.29 L7.2
VCORE_EN: length 72.8
  TOP w0.254: U22.4 86.28,64.55 v1(86.16,64.44) ; v1(101.3,57.04) U26.9
  TOP w0.305: v1(95.79,14.91) 95.79,14.93 95.78,14.94 U38.26
  L3_INT1 w0.254: v1(86.16,64.44) 86.8,63.8 86.8,62.28 92.03,57.04 v1(101.3,57.04) 102.29,56.06 102.29,50.34 98.48,46.53 98.48,31.42 95.56,28.5 95.56,23.42 95.18,23.04 95.18,15.53 v1(95.79,14.91)
  BOTTOM w0.305: R320.1 v1(86.16,64.44) ; v1(101.3,57.04) 101.4,57.14 R327.1
  BOTTOM w0.508: v1(95.79,14.91) 95.79,14.17 C597.1
VPA: length 8.8
  TOP w0.279: U45.22 16.55,80.59 17.58,79.55 17.58,79.04 17.84,78.79 R434.1
  TOP w0.381: C632.1 R434.1
  TOP w0.508: C632.1 19.61,76.5
VPA_PCIE2: length 10.7
  TOP w0.279: U49.22 40.04,87.53 41.08,88.57 41.59,88.57 41.84,88.82 R469.1
  TOP w0.381: C651.1 R469.1
  TOP w0.508: C651.1 46.03,90.6
  vias: v1(45.01,89.46) v1(45.01,88.19) v1(46.16,89.46) v1(46.28,88.19) v1(47.55,90.6) v1(47.55,89.46) v1(47.55,88.19) v1(48.82,88.19) v1(59.37,136.45) v1(59.37,135.18) v1(59.37,133.91) v1(60.64,136.45) v1(60.64,135.18) v1(60.64,133.91) v1(61.91,136.45) v1(61.91,135.18) v1(61.91,133.91)
VR500_1V5: length 25.5
  TOP w0.254: U38.13 89.13,17.11 85.78,13.76 83.5,13.76
  TOP w0.508: P3.28 v1(46.12,135.98) ; P3.6 v1(46.03,123.98) ; P2.48 v1(26.35,54.02) ; P3.48 v1(46.2,143.98) ; P2.6 v1(46.35,54.02) ; P2.28 v1(34.35,54.03)
  BOTTOM w0.381: v1(46.35,54.02) 46.28,54.09 C321.1 ; C324.1 26.47,54.15 v1(26.35,54.02) ; v1(34.35,54.03) 34.22,54.16 C322.1
  BOTTOM w0.508: v1(46.2,143.98) 46.24,143.94 C458.1 ; v1(46.12,135.98) 46.2,136.07 C457.1 ; C456.1 46.05,124 v1(46.03,123.98) ; C463.1 46.54,128.45 v1(46.03,127.94) ; C326.1 v1(41.41,53.06)
  vias: v1(80.7,30.66) v1(80.7,29.51) v1(80.7,28.62) v1(80.7,27.86) v1(80.7,26.97) v1(80.7,26.08) v1(81.59,26.72) v1(81.84,29.51)
N17321635: length 42
  TOP w0.127: v2(147,60.41) 146.6,60.81 U21.E16
  TOP w0.152: Q9.2 v1(177.98,45.77) R143.1
  BOTTOM w0.122: 150.55,59.99 148.39,59.99 147.98,60.41 v2(147,60.41)
  BOTTOM w0.152: v1(177.98,45.77) 177.35,46.4 177.35,49.71 168.08,58.98 152.58,58.98 151.57,59.99 150.55,59.99
N17423556: length 4.8
  TOP w0.152: J13.6 v1(200.21,36.62)
  BOTTOM w0.152: R370.2 v1(200.21,36.62)
N23886013: length 2.8
  TOP w0.152: C5.1 v1(183.06,149.78) 182.33,149.78 182.17,149.93 U2.2
N23886021: length 9.1
  TOP w0.152: C8.2 184.84,148.38 184.59,148.13 v1(181.67,148.13) 180.27,148.13 179.63,148.77 179.63,150.42 179.8,150.58 U2.3
N23886023: length 3
  TOP w0.152: C8.1 v1(182.82,148.77) 182.3,149.28 U2.1
N23886031: length 2.9
  TOP w0.152: U2.6 182.34,152.53 v1(182.68,152.19) C3.1
N23886069: length 2.9
  TOP w0.152: U2.4 182.12,151.23 v1(182.56,150.8) C4.2
N23886074: length 4.4
  TOP w0.152: C4.1 184.84,151.05 184.46,151.43 v1(183.44,151.43) 182.68,151.43 182.23,151.88 U2.5
N23887688: length 23.5
  TOP w0.508: BT1.1 BT1.2 124.48,105.08 C60.1 118.17,105.08 117.53,104.44 R84.2
N24081686: length 2.5
  TOP w0.254: 87.18,17.83 88.45,17.83 88.73,18.11 U38.11
N24082962: length 1.6
  TOP w0.254: 93.78,14.28 U38.22
N24085678: length 1.6
  TOP w0.254: 93.28,14.28 U38.21
N24088889: length 4.1
  TOP w0.152: U38.39 98.58,21.61 100.39,23.42 TP19.1
N24089783: length 3.4
  TOP w0.203: C147.1 C145.2
  TOP w0.254: C145.2 97.72,15.92 97.5,16.14 U38.29
N24092126: length 2.2
  TOP w0.254: C125.1 92.78,24.83 U38.51
N24092316: length 2.4
  TOP w0.254: U38.49 93.78,24.3 93.91,24.43 93.91,24.94 94.67,25.7 C126.1
N24092557: length 2
  TOP w0.254: C124.1 92.28,25.47 U38.52
N24092669: length 1.2
  TOP w0.254: C129.1 96.78,24.94 U38.43
N24105172: length 19
  TOP w0.203: U1.32 89.8,150.46 89.97,150.29 90.86,150.29 91.24,150.67 91.24,159.31 90.61,159.94 90.23,159.94
  BOTTOM w0.508: R189.1 77.15,154.86 v1(76.64,155.37)
  vias: v1(72.83,157.27) v1(72.83,155.75) v1(74.48,157.27) v1(74.48,155.75)
N24105186: length 4.7
  TOP w0.203: 87.81,155.5 87.8,155.48 U1.6 ; 90.1,155.62 89.8,155.32 U1.1 90.35,154.73 90.35,154.73 ; U1.5 88.2,155.49 88.19,155.5
  TOP w0.508: 89.33,158.42 C1.2 88.45,157.67
  vias: v1(88.07,157.02) v1(88.07,156.26) v1(88.83,157.15) v1(89.59,157.91) v1(89.59,157.15)
N24105908: length 2.4
  TOP w0.203: U1.3 89,155.33 v1(88.83,155.5)
  BOTTOM w0.152: v1(88.83,155.5) 89.46,154.86 R185.2
N24106035: length 21.2
  TOP w0.203: U1.18 84.2,150.23 v1(83.75,149.78) ; v1(90.99,146.86) 90.48,147.37 TP3.1 89.46,149.02 89.46,149.42 88.6,150.29 U1.29
  L4_INT2 w0.203: v1(90.99,146.86) 90.99,147.37 90.1,148.26 85.27,148.26 v1(83.75,149.78)
  BOTTOM w0.508: v1(83.75,149.78) 82.61,148.64 R192.1 C181.1 R189.2
N24106207: length 4.9
  TOP w0.203: U1.16 83.8,155.19 83.62,155.37 v1(82.61,155.37)
  BOTTOM w0.381: v1(82.61,155.37) 82.23,155.75 R2.2 R1.1
N24106733: length 21.5
  TOP w0.203: v1(86.16,155.88) 86.2,155.84 U1.10
  L4_INT2 w0.508: v1(79.18,144.96) 79.18,153.59 82.61,157.02 85.78,157.02 v1(86.16,156.64) v1(86.16,155.88)
  BOTTOM w0.508: v1(79.18,144.96) R187.2 78.16,143.56
N24106981: length 14.7
  TOP w0.508: 74.91,141.53 C183.1 ; C183.1 76.64,140.33 ; C183.1 78.37,141.53 ; L9.2 73.64,140.05 ; L9.2 71.56,141.06 ; L9.2 69.48,140.05 ; L9.2 71.56,139.05
  BOTTOM w0.508: 77.54,142.54 R188.1 ; R188.1 78.16,141.92 ; R188.1 78.78,142.54 ; 81.16,141.27 R195.1 81.97,140.08
  vias: v1(78.67,140.13) v1(78.92,141.91) v1(78.92,141.02) v1(79.62,142.29) v1(79.62,141.4) v1(79.62,140.18) v1(86.29,139.11) v1(87.18,139.11) v1(88.19,139.11) v1(88.19,138.22) v1(89.08,139.11) v1(89.08,138.22)
N24107203: length 3.5
  TOP w0.203: R14.1 88.45,149.78 87.94,150.29 86.8,150.29 86.6,150.49 U1.24
N24107357: length 4.5
  TOP w0.203: v1(83.24,150.93) U1.17
  BOTTOM w0.508: v1(83.24,150.93) 82.6,150.29 C178.2 C177.2
N24107470: length 29.8
  TOP w0.203: v1(87.05,155.62) 86.92,155.62 86.6,155.3 U1.9
  L4_INT2 w0.635: v1(75.24,136.7) 77.15,136.7 80.32,139.88 80.32,151.43 83.62,154.73 86.42,154.73 87.05,155.37 v1(87.05,155.62)
  L4_INT2 w0.762: v1(87.05,155.62) v1(87.05,156.39)
  BOTTOM w0.635: R196.1 v1(75.24,136.7)
N24107483: length 2
  BOTTOM w0.635: R196.2 C188.1
N24107486: length 2.5
  BOTTOM w0.635: C188.2 T1.1
N24107616: length 4.2
  BOTTOM w0.508: T1.6 73.97,124.51 C208.1
N24107621: length 7.9
  BOTTOM w0.508: C208.2 R208.2 73.58,120.69 D25.3 73.59,118.02 R204.2
N24107777: length 8.9
  BOTTOM w0.508: Q3.4 82.35,122.86 81.79,122.3 Q18.2 81.08,123.24 80.7,123.62 77.91,123.62 77.53,123.24 Q17.2
N24107780: length 7.3
  BOTTOM w0.508: Q18.1 79.05,121.57 78.69,121.21 75.72,121.21 75.47,121.46 Q17.1 73.67,122.3 R208.1
N24107840: length 7.5
  BOTTOM w0.508: Q18.3 80.78,120.11 81.08,119.81 C40.1 R47.2 R61.2
N24107947: length 3.5
  BOTTOM w0.508: R47.1 83.37,115.36 84,116 D7.C
N24107950: length 4.1
  TOP w0.508: T2.6 86.85,122.58 ; T2.6 87.76,121 ; T2.6 86.85,119.43
  vias: v1(91.37,121.21) v1(91.37,119.94) v1(91.37,118.67) v1(92.51,121.21) v1(92.51,119.94) v1(92.64,118.67)
N24108405: length 6.9
  BOTTOM w0.508: R42.2 93.83,125.65 ; R42.2 92.64,126.46 ; R42.2 91.45,125.65 ; R42.2 92.64,124.84 ; C27.1 90.05,127.23 ; C27.1 90.05,125.09 ; C27.1 90.8,126.16
N24108952: length 3.6
  TOP w0.203: R13.1 85.78,148.51 85,149.3 U1.20
N24109652: length 4.4
  TOP w0.203: U1.21 85.4,149.66 86.16,148.89 v1(86.92,148.89)
  BOTTOM w0.203: C184.1 87.18,148.64 v1(86.92,148.89)
N24109671: length 2.7
  TOP w0.203: U1.22 85.8,150.02 v1(86.19,149.63)
  BOTTOM w0.203: v1(86.19,149.63) 86.04,149.78 R191.1
N24109742: length 3.8
  TOP w0.203: R3.1 84.26,157.4 85.02,156.64 85.02,155.5 85.4,155.12 U1.12
N24109897: length 3.6
  TOP w0.203: v1(83.5,156.26) 83.75,156.26 84.2,155.81 U1.15
  BOTTOM w0.203: v1(83.5,156.26) 84.26,156.26 84.77,155.75 C173.1
N24109974: length 3.5
  TOP w0.203: U1.23 86.2,150.38 86.8,149.78 v1(87.69,149.78)
  BOTTOM w0.203: R190.1 87.43,150.04 v1(87.69,149.78)
N24109983: length 3.7
  TOP w0.203: R4.1 85.4,157.4 85.4,155.62 85.8,155.23 U1.11
N24110294: length 4.4
  TOP w0.203: C174.1 82.86,158.04 84.6,156.3 U1.14
N24133241: length 13.1
  TOP w0.533: 65.99,158.37 J1.1 ; J1.1 65.99,160.53 ; J1.1 68.3,159.45 ; J1.1 63.68,159.45 ; R5.1 67.62,156.63 ; R5.1 66.87,155.75 ; R5.1 67.62,154.87 ; 63.82,152.07 F1.1 ; F1.1 65.08,153.32 ; F1.1 66.34,152.07
N24137908: length 3
  TOP w0.254: U22.21 93.52,64.55 C89.1
N24137912: length 1
  BOTTOM w0.508: v1(93.58,62.94) 93.55,62.91 C405.2
N24137946: length 2.1
  TOP w0.254: v1(91.62,63.93) 91.5,64.05 U22.20
  BOTTOM w0.254: C405.1 v1(91.62,63.93)
N24137962: length 5.3
  TOP w0.254: U22.24 91.08,66.05 91.75,66.72 R128.1 C87.2 R127.2
N24138040: length 2.1
  TOP w0.254: R129.1 86.54,65.2 86.69,65.05 U22.3
N24138143: length 2.5
  TOP w0.254: U22.2 87.21,65.55 86.16,66.6 C88.1
N24145679: length 39.2
  TOP w0.254: v1(96.45,82.98) 96.72,82.71 U19.23 ; v1(100.26,79.94) U19.15 ; v1(97.71,77.4) U19.10 ; U19.21 97.71,82.85 97.72,82.85 97.72,82.98 v1(97.85,83.11) R105.1 ; v1(100.26,81.44) U19.18
  BOTTOM w0.508: v1(96.45,82.98) 95.94,82.47 C305.1 95.05,82.47 94.67,82.09 94.67,80.82 95.31,80.19 95.31,77.52 96.2,76.63 97.47,76.63 97.97,76.12 ; 101.15,80.69 101.15,81.84 99.88,83.11 C302.1 v1(97.85,83.11) ; 101.15,80.69 C309.1 100.13,81.31 v1(100.26,81.44) ; 101.15,80.69 101.15,79.17 ; 97.97,76.12 98.48,76.63 C318.1 97.72,77.39 v1(97.71,77.4) ; 97.97,76.12 C325.1 99.24,75.49 101.15,77.39 101.15,79.17 ; 101.15,79.17 C314.1 100.13,79.81 v1(100.26,79.94)
  BOTTOM w0.635: C325.1 C327.1 98.03,73.91 L26.1
N24145732: length 4.4
  TOP w0.254: U19.5 94.68,79.44 v1(94.54,79.3)
  BOTTOM w0.508: C313.1 C319.1 ; C313.1 R263.2 ; C313.1 v1(94.54,79.3)
N24145752: length 14.5
  TOP w0.254: v1(97.22,83.74) U19.22
  BOTTOM w0.508: R263.1 93.78,82.09 92.89,82.98 C304.1 91.75,83.61 92.13,84 96.96,84 v1(97.22,83.74) 97.21,83.74 C303.1
  BOTTOM w0.762: C304.1 90.73,82.98 90.35,83.36 L25.2
N24151368: length 10
  TOP w0.254: U19.4 94.3,79.94 94.16,79.8 R112.2 C86.1 92.39,79.17 92.13,78.92 87.94,78.92 87.39,79.47 Y5.1
N24151377: length 7.1
  TOP w0.254: Y5.3 91.97,81.87 92.39,81.46 C85.1 R112.1 94.29,80.82 94.68,80.43 U19.3
N24157795: length 4.8
  TOP w0.254: U19.24 96.22,82.45 94.8,83.87 R104.2 R105.2
N24157798: length 22.6
  TOP w0.152: R126.1 R125.1 85.02,74.6 J12.3 84,72.69 85.02,71.68 91.24,71.68 96.72,77.15 U19.8
N24157984: length 6.6
  TOP w0.104: U19.20 98.22,82.47 98.35,82.61 98.35,82.98 98.69,83.31 100.16,83.31 101.7,84.84 102.19,84.84 102.29,84.95 R106.1
N24157991: length 6
  TOP w0.104: U19.19 98.72,82.49 98.66,82.55 98.66,82.85 98.81,83.01 100.29,83.01 101.82,84.54 102.19,84.54 102.29,84.44 R108.1
N24158001: length 3.9
  TOP w0.104: R113.1 102.29,80.37 102.13,80.53 100.04,80.53 99.94,80.43 U19.16
N24158003: length 3.8
  TOP w0.104: R110.1 102.29,80.94 102.19,80.84 100.04,80.84 99.94,80.93 U19.17
N24158101: length 5.6
  TOP w0.104: R116.1 102.29,76.95 102.19,76.84 101.74,76.84 101.15,77.44 101.15,78.66 100.47,79.34 100.04,79.34 99.94,79.44 U19.14
N24158103: length 5.6
  TOP w0.104: R121.1 102.29,76.44 102.19,76.54 101.62,76.54 100.85,77.31 100.85,78.54 100.35,79.03 100.04,79.03 99.94,78.94 U19.13
N24158105: length 3.2
  TOP w0.104: U19.12 98.72,77.71 98.63,77.63 98.63,75.97 98.86,75.74 R124.1
N24158107: length 3.2
  TOP w0.104: U19.11 98.22,77.71 98.33,77.6 98.33,75.97 98.1,75.74 R123.1
N24158224: length 46.4
  TOP w0.104: R123.2 97.97,74.22 98.33,73.86 98.33,73.56 94.59,69.82 70.03,69.82 65.3,74.56 65.3,76.91 65.4,77.01 ; U43.3 65.14,80.35 64.96,80.53 64.81,80.53 64.49,80.21 64.49,78.53 65.3,77.73 65.3,77.11 65.4,77.01 ; 65.4,77.01 R345.1
N24158233: length 47.9
  TOP w0.104: U43.4 65.14,81 64.96,80.83 64.69,80.83 64.19,80.33 64.19,78.41 64.99,77.61 64.99,77.11 64.89,77.01 ; R350.1 64.89,77.01 ; 64.89,77.01 64.99,76.91 64.99,74.43 69.91,69.52 94.72,69.52 98.63,73.43 98.63,73.86 98.99,74.22 R124.2
N24158614: length 30.6
  TOP w0.152: U19.9 97.22,77.14 91.37,71.3 83.5,71.3 82.48,72.31 82.48,77.14 J12.1 85.27,78.66 86.04,77.9 R115.1 R119.1
N24164336: length 2.4
  TOP w0.152: R355.1 68.5,83.6 U43.8
N24164341: length 2.4
  TOP w0.152: R335.1 68.48,79.7 U43.2
N24164581: length 5.7
  TOP w0.104: U43.14 60.96,80.35 61.14,80.53 61.39,80.53 61.6,80.31 61.6,78.87 60.97,78.23 60.97,77.47 60.64,77.14 R333.1
N24164584: length 6.5
  TOP w0.104: R347.1 61.65,77.14 61.27,77.52 61.27,78.11 61.91,78.74 61.91,80.44 61.52,80.83 61.14,80.83 60.96,81 U43.13
N24164587: length 6.1
  TOP w0.104: R351.1 62.16,85.65 61.8,85.29 61.8,82.22 61.41,81.83 61.14,81.83 60.96,81.65 U43.12
N24164590: length 5.6
  TOP w0.104: U43.11 60.96,82.3 61.14,82.13 61.28,82.13 61.5,82.35 61.5,85.29 61.14,85.65 R357.1
N24169528: length 3.6
  TOP w0.305: R85.2 R87.1 135.18,112.95 135.84,112.3 U11.7
N24185665: length 5.7
  TOP w0.104: U8.U4 153.9,121.11 153.9,117.35 v1(154.23,117.02) C57.2
N24185672: length 4.6
  TOP w0.104: C56.2 v1(153.09,117.02) 153.6,117.52 153.6,120.43 153.45,120.58 U8.V4
N24186431: length 5.9
  TOP w0.152: v1(168.84,125.14) 166.88,125.14 U8.N17
  BOTTOM w0.152: v1(168.84,125.14) 169.36,125.65 R222.2
N24186507: length 3.2
  TOP w0.152: v1(153.98,132.13) U8.F5
  BOTTOM w0.152: R209.2 152.33,131.87 152.58,131.62 153.47,131.62 v1(153.98,132.13)
N24186703: length 18.6
  TOP w0.152: v1(153.93,129.08) U8.J4
  L3_INT1 w0.127: v1(160.33,139.49) 160.33,136.7 159.44,135.81 159.44,133.91 159.08,133.55 153.62,133.55 153.47,133.4 153.47,129.54 v1(153.93,129.08)
  BOTTOM w0.152: R201.2 159.57,140.26 v1(160.33,139.49)
N24186832: length 8.3
  TOP w0.254: U8.F18 169.09,132.58 169.4,132.89 C31.1 170.62,133.65 171.3,134.33 v1(172.52,134.33) Y3.1
N24187101: length 3.4
  TOP w0.254: U8.G18 v1(169.18,131.58) 169.26,131.58 169.73,131.11 R52.2
N24187104: length 30.7
  TOP w0.152: U8.L14 v1(163.9,128.05)
  L4_INT2 w0.127: J7.1 177.98,143.69 177.98,135.3 173.28,130.6 163.76,130.6 163.38,130.22 163.38,128.57 v1(163.9,128.05)
N24187111: length 31.4
  TOP w0.152: U8.M16 v1(165.93,127.08)
  L4_INT2 w0.127: J7.2 179.89,142.92 181.29,141.53 181.29,129.21 179.16,127.08 v1(165.93,127.08)
N24187118: length 23.9
  TOP w0.152: U8.K14 v1(163.91,129.06)
  L4_INT2 w0.127: v1(163.91,129.06) 163.99,129.06 164.52,129.59 168.08,129.59 168.59,129.08 172.4,129.08 178.36,135.05 178.36,138.99 J7.3
N24187125: length 29.9
  TOP w0.152: U8.M15 v1(164.93,127.08)
  L4_INT2 w0.127: v1(164.93,127.08) 164.94,127.08 165.41,127.56 179,127.56 180.9,129.46 180.9,136.7 J7.4
  BOTTOM w0.152: R202.1 J7.4
N24187168: length 18.5
  TOP w0.152: U8.L15 v1(164.91,128.06)
  L4_INT2 w0.127: v1(164.91,128.06) 165.43,128.57 172.52,128.57 179.25,135.3 J7.5
N24187336: length 2.7
  TOP w0.152: U8.A10 v1(159.43,139.11) 159.43,140.25 R20.2
N24187387: length 3.9
  TOP w0.152: v1(168.57,133.41) 168.48,133.33 168.48,133.3 168.32,133.14 166.99,133.14 U8.F17
  BOTTOM w0.152: v1(168.57,133.41) 168.59,133.4 R203.1
N24187390: length 10
  TOP w0.152: v1(162.24,139.11) 162.24,139.88 161.85,140.26 R21.1 ; U8.G13 v1(162.93,132.08)
  L3_INT1 w0.127: v1(162.24,139.11) 162.4,138.95 162.4,132.6 v1(162.93,132.08)
N24187475: length 2.9
  TOP w0.152: U8.H3 v1(152.9,131.05)
  BOTTOM w0.152: R212.1 151.31,130.35 152.01,131.05 v1(152.9,131.05)
N24187514: length 11.7
  TOP w0.152: J8.3 R75.1 172.4,125.91 167.72,130.58 U8.H18
N24187517: length 17.1
  TOP w0.152: J8.1 R76.1 173.16,120.83 171.63,122.35 171.63,126.16 167.7,130.1 166.92,130.1 U8.H17
N24187752: length 8.4
  TOP w0.152: U8.K15 v1(164.92,129.07)
  BOTTOM w0.152: v1(164.92,129.07) 165.41,128.57 170.62,128.57 R219.1
N24187759: length 3.2
  TOP w0.152: U8.J15 v1(163.9,130.11)
  BOTTOM w0.129: v1(163.9,130.11) 163.96,130.17 R205.1
N24187766: length 7.1
  TOP w0.152: U8.J16 v1(165.93,130.08)
  BOTTOM w0.152: R215.1 171.38,128.95 170.25,130.08 v1(165.93,130.08)
N24187780: length 8.1
  TOP w0.152: U8.H16 v1(164.9,131.11)
  BOTTOM w0.152: R211.1 168.84,130.73 168.59,130.48 166.55,130.48 165.92,131.11 v1(164.9,131.11)
N24187787: length 2.7
  TOP w0.152: v1(166.93,131.11) 166.47,131.58 U8.G17
  BOTTOM w0.152: R206.1 167.44,131.62 v1(166.93,131.11)
N24189801: length 6.5
  TOP w0.152: v1(170.24,125.02) 170.24,126.29 167.94,128.58 U8.K18
  BOTTOM w0.152: R228.1 169.73,124.51 v1(170.24,125.02)
N24194949: length 24.6
  TOP w0.381: U8.R5 v1(154.93,123.08) ; U8.T12 v1(161.93,122.08) ; U8.T8 v1(156.92,122.07) ; U8.T10 v1(159.93,122.08)
  TOP w0.533: 177.18,107.78 L17.1 ; L17.1 179.29,107.78 ; L17.1 178.24,106.83 ; C64.1 172.94,114.56 ; C64.1 172.94,112.35 ; C64.1 170.88,113.46 ; C64.1 174.99,113.46 ; C78.1 172.94,106.82 ; C78.1 170.88,105.71 ; C78.1 172.94,104.61 ; C78.1 174.99,105.71
  BOTTOM w0.381: C269.1 154.96,123.11 v1(154.93,123.08) ; v1(156.92,122.07) 156.77,121.92 156.77,120.06 ; v1(159.93,122.08) 159.95,122.06 C278.1 ; v1(161.93,122.08) 161.73,121.87 C277.1 C276.2
  vias: v1(171.51,111.43) v1(171.51,110.54) v1(172.65,111.43) v1(172.65,110.54) v1(173.79,111.43) v1(173.79,110.54)
N24197224: length 18.9
  TOP w0.381: U8.T4 v1(152.96,122.1) ; U8.T6 155.43,122.53 v1(155,122.1)
  TOP w0.533: C65.1 160.71,117.33 ; C65.1 160.71,113.21 ; C65.1 161.82,115.27 ; C65.1 159.61,115.27
  BOTTOM w0.508: v1(155,122.1) C273.1 152.96,122.1 v1(152.96,122.1) 152.71,121.86 C274.1 C279.2 152.71,119.56 153.35,118.92 155.76,118.92 v1(157.41,117.27) v1(158.3,117.27)
N24197929: length 7.5
  TOP w0.381: U8.E10 v1(159.92,134.06)
  TOP w0.406: 172.37,146.99 L8.1 ; L8.1 173.32,145.93 ; L8.1 173.32,148.04 ; 173.41,145.67 C13.1 172.22,143.94
  BOTTOM w0.508: v1(159.92,134.06) 159.95,134.1 C212.2
  vias: v1(170.62,143.56) v1(171.63,143.56)
N24198270: length 11.2
  TOP w0.381: v1(167.95,134.03) 167.7,133.78 167.63,133.78 U8.E18 ; v1(167.95,134.03) 168.84,134.92 ; v1(167.95,134.03) 167.89,134.03
  TOP w0.406: 171.61,136.83 L12.1 ; L12.1 172.56,135.77 ; L12.1 172.56,137.88 ; 172.52,138.28 C17.1 ; C17.1 171.33,140 ; C17.1 172.52,141.73
  BOTTOM w0.508: v1(167.95,134.03) 167.44,134.03 166.93,134.54 C213.2
N24220381: length 1.1
  TOP w0.305: U21.G8 v2(145.4,67.61) ; v2(144.6,67.61) U21.H8
N24221237: length 1.1
  TOP w0.305: U21.D4 147.39,70.41 v2(147.8,70.81) ; U21.G7 v2(145.4,68.41)
N24221789: length 1.6
  TOP w0.305: U21.H9 v2(144.6,66.81) ; U21.H10 v2(144.6,66.01)
  BOTTOM w0.127: 145.09,65.58 145.6,65.58
N24222945: length 22.2
  TOP w0.127: v2(145.4,60.41) 145,60.81 U21.G16
  L3_INT1 w0.127: v1(161.6,56.18) 161.6,56.82 161.09,57.33 159.31,57.33 158.81,57.83 153.6,57.83 151.43,60.01 145.8,60.01 v2(145.4,60.41)
  BOTTOM w0.152: v1(161.6,56.18) 163.51,54.28 TP44.1
N24222963: length 6
  TOP w0.127: v2(146.2,60.41) 145.8,60.81 U21.F16
  BOTTOM w0.122: 147.98,59.99 148.74,59.23 150.55,59.23
  BOTTOM w0.127: v2(146.2,60.41) 146.6,60.01 147.96,60.01 147.98,59.99
  BOTTOM w0.152: TP36.1 150.55,59.23
N24242061: length 55.9
  TOP w0.152: v1(168.84,100) 177.09,100 178.49,98.6 J10.1
  TOP w0.305: v2(144.6,70.01) U21.H5
  L3_INT1 w0.127: v2(144.6,70.01) 144.99,70.41 144.99,73.48 149.41,77.9 149.41,80.57 v1(168.84,100)
N24242100: length 57.7
  TOP w0.127: U21.K5 v2(143,70.01)
  TOP w0.152: J11.2 R101.1 178.36,94.92 174.68,98.6 v1(166.81,98.6)
  L3_INT1 w0.127: v2(143,70.01) 143.39,70.41 144.05,70.41 144.2,70.55 144.2,73.17 149.03,78 149.03,80.82 v1(166.81,98.6)
N24244080: length 20.2
  TOP w0.127: v2(144.6,58.81) 144.2,59.21 U21.H18
  L4_INT2 w0.127: v2(144.6,58.81) 144.2,58.41 144.2,56.24 144.2,56.24 144.2,55.42 145.34,54.28 155.12,54.28 v1(156.9,52.5)
  BOTTOM w0.152: 158.55,51.36 158.04,51.36 v1(156.9,52.5)
N24245830: length 6.3
  TOP w0.305: U21.T11 v2(137.4,65.21) ; v2(137.4,62.81) 137.8,63.21 U21.T13 ; v2(137.4,64.41) 137.8,64.01 U21.T12
  BOTTOM w0.508: C422.2 v1(121.98,63.29) ; FL1.1 116.68,62.53 C425.1 119.18,63.17 v1(119.44,63.17) ; C423.2 v1(120.45,63.29)
N24247836: length 7.4
  TOP w0.305: v2(135.8,62.81) 136.2,63.21 U21.V13 ; v2(135.8,64.41) 136.2,64.01 U21.V12 ; U21.V11 v2(135.8,65.21) ; v2(135.8,62.01) 136.2,62.41 U21.V14 ; U21.V10 v2(135.8,66.01)
  BOTTOM w0.305: C426.1 135.96,61.83 135.96,61.85 v2(135.8,62.01)
  BOTTOM w0.508: v1(119.06,57.33) C450.1 FL2.1 ; C452.2 v1(120.83,57.45) ; C451.2 v1(122.1,57.45)
N24271003: length 19.8
  TOP w0.305: U21.H6 v2(144.6,69.21)
  L3_INT1 w0.254: v1(145.22,77.26) 143.57,75.61 142.17,75.61 140.39,73.84 140.39,70.15 141.41,69.14 143.06,69.14 143.45,68.75 144.13,68.75 v2(144.6,69.21)
  BOTTOM w0.254: v1(145.22,77.26) 145.85,77.9 C315.1 R273.2 ; C333.1 145.09,70.41 145.09,69.71 v2(144.6,69.21)
N24271010: length 14.8
  TOP w0.305: U21.J6 v2(143.8,69.21)
  L4_INT2 w0.254: v1(144.2,77.14) 140.9,73.84 140.9,69.77 141.15,69.52 143.49,69.52 v2(143.8,69.21)
  BOTTOM w0.254: v1(144.2,77.14) C316.1 R274.2
N24271066: length 6.4
  TOP w0.127: U21.L17 141.8,60.01 v2(142.2,59.61)
  BOTTOM w0.508: 158.55,53.64 C462.1 156.9,55.04 155.5,56.44 v1(155.5,57.2)
N24275030: length 24.1
  TOP w0.152: U21.Y7 v2(134.2,68.41)
  BOTTOM w0.254: v2(134.2,68.41) 133.72,68.88 133.15,68.88 132.9,68.63 131.63,68.63 129.85,70.41 125.41,70.41 123.75,72.06 123.75,74.09 123.5,74.34 C328.1
  BOTTOM w0.381: R294.1 v1(115.88,74.85) C330.1 119.56,74.85 120.07,74.34 C329.1 C328.1
